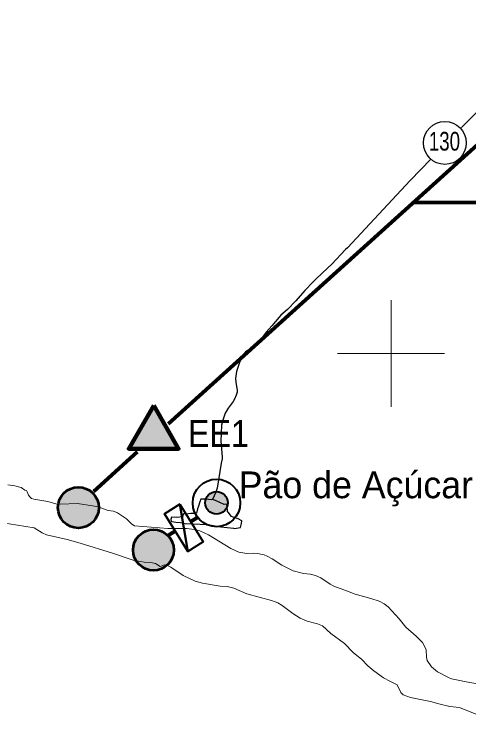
# Model space of a CAD drawing. Extents: x 553962 to 842807, y 8883888 to 9032388.
# Drawn here: x 667945 to 676457, y 8918221 to 8931350 of the extents above; entities that cross this region are included whole.
import ezdxf
from ezdxf.enums import TextEntityAlignment as Align

# ---------------------------------------------------------------- set-up
doc = ezdxf.new("R2010")
doc.units = 0
doc.header["$LTSCALE"] = 200
for name, color, linetype, lineweight in [('12', 7, 'Continuous', 25), ('2', 7, 'Continuous', 13), ('21', 7, 'Continuous', 25), ('25', 7, 'Continuous', 13), ('28', 7, 'Continuous', 40), ('41', 7, 'Continuous', 40), ('48', 7, 'Continuous', 25), ('57', 7, 'Continuous', 13)]:
    doc.layers.add(name, color=color, linetype=linetype, lineweight=lineweight)

msp = doc.modelspace()

# ---------------------------------------------------------------- hatches: boundary and pattern name
at = {"layer": '28'}
for points in [[(670559.1, 8924026.5), (671025.2, 8923219.1), (670093, 8923219.1)], [(669497.4, 8921960.8, 1), (668800.8, 8922275.4, 1)], [(671944.5, 8922205.8, 1), (671523.6, 8922205.8, 1)], [(670936.5, 8921324.9, 1), (670172.2, 8921324.9, 1)]]:
    msp.add_hatch(color=256, dxfattribs=at).paths.add_polyline_path(points)

# ---------------------------------------------------------------- linework, layer by layer
at = {"layer": '12'}
for points in [[(677127.3, 8930051.6), (676803, 8929714.4), (676539.8, 8929451), (676316.9, 8929228)], [(675747.8, 8928644.7), (675357.8, 8928239.4), (674183.6, 8926978.8), (674145.1, 8926947.6), (673889.8, 8926674.1), (673817.5, 8926604.1)], [(673817.5, 8926604.1), (673601, 8926394.6), (673540.7, 8926341.3), (673385.9, 8926177.5), (673220, 8925987.8), (673060.2, 8925824.4), (672938.9, 8925717.3), (672905.6, 8925678)], [(672905.6, 8925678), (672769.2, 8925517), (672663.1, 8925399.6), (672486.7, 8925159.8), (672402.7, 8925104), (672277.3, 8925032.8), (672246.2, 8924995.7), (672220.2, 8924955.3), (672176.2, 8924860.7)], [(672176.2, 8924860.7), (672161.6, 8924829.2), (672110.6, 8924662), (672086.1, 8924531.1), (672095.5, 8924466.4)], [(672095.5, 8924466.4), (672118.8, 8924306.3), (672118.5, 8924278.5), (672104, 8924223.3), (672070.6, 8924145.4), (672047.1, 8924105), (671951.4, 8923978.3), (671897.8, 8923887.3), (671849.3, 8923755.3), (671827.1, 8923657.7), (671813, 8923357.8), (671840.2, 8923069), (671838.2, 8923027.3), (671822.3, 8922948), (671796.6, 8922795.7)], [(671796.6, 8922795.7), (671743.5, 8922481.6), (671721, 8922405.8), (671692.6, 8922335.7), (671657.6, 8922270.9)]]:
    msp.add_lwpolyline(points, dxfattribs=at)
at = {"layer": '2'}
for p, q in [((675000, 8924000), (675000, 8926000)), ((674000, 8925000), (676000, 8925000))]:
    msp.add_line(p, q, dxfattribs=at)
at = {"layer": '21'}
msp.add_lwpolyline([(672070.8, 8921729.3), (672183.6, 8921744.1), (672204.3, 8921823.7), (672205.8, 8921869.8), (672137.9, 8921906.6), (672045.5, 8921936.8), (672015.8, 8921950.8), (671951.1, 8922034), (671936.7, 8922041.8), (671940.3, 8922071), (671928.8, 8922182.7), (671874.6, 8922176.6), (671712.4, 8922251.7), (671659.2, 8922270.3), (671636.6, 8922261.5), (671534.1, 8922275.4), (671438.6, 8922277.6), (671419.5, 8922227.5), (671398.3, 8922143), (671378.3, 8922092.9), (671356.9, 8922015.4), (671328.1, 8922006.3), (671250.4, 8922007.9), (671162.4, 8921997.4), (671116.6, 8922002), (671109.5, 8921989.5), (671105, 8921961.4), (671096.8, 8921948), (670990.1, 8921931.4), (670891.9, 8921937.6), (670878.8, 8921896.3), (670882.6, 8921866.1), (670900, 8921857.8), (670970.5, 8921845.4), (671059.8, 8921839.3), (671147.8, 8921823.2), (671572.8, 8921799.1), (671817.6, 8921756.7), (672050.9, 8921730.4)], close=True, dxfattribs=at)
at = {"layer": '25'}
for points in [[(667827.1, 8922544.8), (667960.2, 8922528.3), (668076.2, 8922494.1), (668149.9, 8922444.5), (668175.3, 8922440.9), (668193.4, 8922414.2), (668215.8, 8922353.1), (668240.8, 8922316.8), (668270.3, 8922290.6), (668317.3, 8922273.5), (668576.3, 8922231.4), (668724.7, 8922190.8), (668817.5, 8922180.4), (669130.5, 8922192.7), (669530, 8922132.2)], [(670613, 8921062.4), (670594.6, 8921075.1), (670505.7, 8921092.1), (670378.9, 8921097.7), (670172.5, 8921136.1), (669790.2, 8921268), (669181.6, 8921455.5), (668940.4, 8921522.2), (668553.3, 8921609.1), (668470.6, 8921646), (668322.8, 8921739.3), (667855.1, 8921816.8), (666980.9, 8921915.9), (665565.9, 8922078.1), (665402.5, 8922087.8), (665227.8, 8922071.5), (665027.5, 8922015.6), (664640.9, 8921845.5), (664531.1, 8921815.4)], [(669530, 8922132.2), (669551.5, 8922120.6), (669703.5, 8922065.4), (669805.2, 8922048.5), (669880.3, 8922022.2), (670051.3, 8921908.8), (670147.5, 8921810.8), (670198.9, 8921779.1), (670825.1, 8921729), (671173.4, 8921726.6), (671321.6, 8921707.8), (671424.1, 8921682), (671582.7, 8921606.9), (672004.6, 8921350.8), (672150.9, 8921284.8), (672299, 8921260.5), (672419, 8921266.9), (672503.5, 8921262.1), (672626.2, 8921231.8), (672681.9, 8921209.8), (672776.3, 8921157.4), (672954.4, 8921040.4), (673169, 8920938.3), (673363.4, 8920887.3), (673485, 8920874.1), (673583.2, 8920848.3), (673683.5, 8920804.3), (673860.5, 8920685.6), (673931.7, 8920649.3), (674185.8, 8920553)], [(674298.5, 8919404.1), (674291.8, 8919409.6), (674126, 8919575.4), (673873, 8919765.1), (673715.5, 8919905.3), (673623, 8919941.7), (673428.6, 8919993.5), (673296.8, 8920049), (673159.2, 8920137.6), (672965, 8920287.3), (672880.8, 8920337.6), (672764.4, 8920379.9), (672301.8, 8920503.9), (672059.4, 8920609.5), (671934.4, 8920643.4), (671799.8, 8920650.2), (671472.2, 8920703.7), (671336.9, 8920745), (671109.4, 8920850.7), (670878.6, 8921005.6), (670802.7, 8921042.5), (670751.6, 8921047.3), (670704.9, 8921020.2), (670678.6, 8921017.5), (670613, 8921062.4)], [(674185.8, 8920553), (674331.2, 8920497.9), (674621.4, 8920420.9), (674779.7, 8920369.3), (674871.4, 8920317.9), (674944.3, 8920262), (675153.1, 8920035), (675278.2, 8919884.7), (675471.8, 8919715.9), (675585, 8919594.2), (675613.6, 8919553.2), (675656.7, 8919458.2), (675661.4, 8919317.4), (675675.3, 8919257.8), (675757.5, 8919139.9), (675867.5, 8919047.4), (676076.8, 8918937.9), (676128.1, 8918918.2), (676257.4, 8918887.3), (676406.6, 8918860.2)], [(676667.5, 8918220.7), (676277.6, 8918381.7), (676099, 8918399.2), (675895.4, 8918446.5), (675739.5, 8918492.1), (675362.3, 8918567.1), (675228.4, 8918616), (675184.7, 8918661.3), (675115.9, 8918805.8), (674978.6, 8918869.4), (674860.2, 8918934.9), (674677.5, 8919067.2), (674567.5, 8919159.4), (674447.6, 8919281.5), (674298.5, 8919404.1)], [(676406.6, 8918860.2), (676902.1, 8918770.1), (677144.9, 8918707)]]:
    msp.add_lwpolyline(points, dxfattribs=at)
at = {"layer": '28', "lineweight": 80}
for p, q in [((681278.6, 8933129.5), (670829.6, 8923682.8)), ((675416.7, 8927829.9), (680156.3, 8927819.3)), ((670250.4, 8923159.2), (669429.3, 8922416.9)), ((671243, 8921855), (671373.4, 8921934.2)), ((670809.3, 8921591.5), (670954.9, 8921680))]:
    msp.add_line(p, q, dxfattribs=at)
at = {"layer": '28', "lineweight": 90}
msp.add_lwpolyline([(670559.1, 8924026.5), (671025.2, 8923219.1), (670093, 8923219.1)], close=True, dxfattribs=at)
at = {"layer": '28'}
msp.add_lwpolyline([(671050.1, 8922182.4), (671486, 8921476.3), (671195.1, 8921296.7), (670759.2, 8922002.8)], close=True, dxfattribs=at)
for points in [[(671050.1, 8922182.4), (670759.2, 8922002.8), (671195.1, 8921296.7)], [(671050.1, 8922182.4), (671195.1, 8921296.7), (671050.1, 8922182.4)]]:
    msp.add_lwpolyline(points, dxfattribs=at)
for radius in [444.4, 210.4]:
    msp.add_circle((671734, 8922205.8), radius, dxfattribs=at)
at = {"layer": '28', "lineweight": 53}
for centre in [(669149.1, 8922118.1), (670554.3, 8921324.9)]:
    msp.add_circle(centre, 382.2, dxfattribs=at)
at = {"layer": '48'}
msp.add_circle((676006.2, 8928939.6), 401.3, dxfattribs=at)
at = {"layer": '57'}
for points in [[(667827.1, 8922544.8), (667960.2, 8922528.3), (668076.2, 8922494.1), (668149.9, 8922444.5), (668175.3, 8922440.9), (668193.4, 8922414.2), (668215.8, 8922353.1), (668240.8, 8922316.8), (668270.3, 8922290.6), (668317.3, 8922273.5), (668576.3, 8922231.4), (668724.7, 8922190.8), (668817.5, 8922180.4), (669130.5, 8922192.7), (669530, 8922132.2)], [(669530, 8922132.2), (669551.5, 8922120.6), (669703.5, 8922065.4), (669805.2, 8922048.5), (669880.3, 8922022.2), (670051.3, 8921908.8), (670147.5, 8921810.8), (670198.9, 8921779.1), (670825.1, 8921729), (671173.4, 8921726.6), (671321.6, 8921707.8), (671424.1, 8921682), (671582.7, 8921606.9), (672004.6, 8921350.8), (672150.9, 8921284.8), (672299, 8921260.5), (672419, 8921266.9), (672503.5, 8921262.1), (672626.2, 8921231.8), (672681.9, 8921209.8), (672776.3, 8921157.4), (672954.4, 8921040.4), (673169, 8920938.3), (673363.4, 8920887.3), (673485, 8920874.1), (673583.2, 8920848.3), (673683.5, 8920804.3), (673860.5, 8920685.6), (673931.7, 8920649.3), (674185.8, 8920553)], [(674185.8, 8920553), (674331.2, 8920497.9), (674621.4, 8920420.9), (674779.7, 8920369.3), (674871.4, 8920317.9), (674944.3, 8920262), (675153.1, 8920035), (675278.2, 8919884.7), (675471.8, 8919715.9), (675585, 8919594.2), (675613.6, 8919553.2), (675656.7, 8919458.2), (675661.4, 8919317.4), (675675.3, 8919257.8), (675757.5, 8919139.9), (675867.5, 8919047.4), (676076.8, 8918937.9), (676128.1, 8918918.2), (676257.4, 8918887.3), (676406.6, 8918860.2)], [(676406.6, 8918860.2), (676902.1, 8918770.1), (677144.9, 8918707)]]:
    msp.add_lwpolyline(points, dxfattribs=at)

# ---------------------------------------------------------------- texts
at = {"layer": '28', "width": 0.9}
msp.add_text('EE1', height=500, dxfattribs=at).set_placement((671200.8, 8923253.6))
at = {"layer": '41'}
msp.add_text('Pão de Açúcar', height=500, dxfattribs=at).set_placement((672147.8, 8922293.7))
at = {"layer": '48', "width": 0.75}
msp.add_text('130', height=350, dxfattribs=at).set_placement((675998.5, 8928796.1), align=Align.CENTER)

doc.saveas('drawing.dxf')
